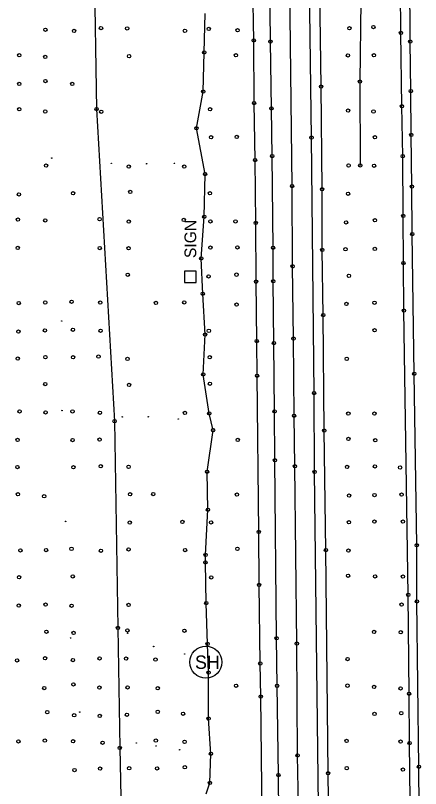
# Model space of a CAD drawing. Extents: x 20503438 to 20508873, y 7964251 to 7984667.
# Drawn here: x 20505218.6 to 20505461, y 7982806.9 to 7983269.7 of the extents above; entities that cross this region are included whole.
import ezdxf

# ---------------------------------------------------------------- set-up
doc = ezdxf.new("R2010")
doc.units = 0
for name, color, linetype in [('SurBreakLine', 7, 'Continuous'), ('SurControl', 7, 'Continuous'), ('SurDrainageArrowDown', 7, 'Continuous'), ('SurDrainageArrowUp', 7, 'Continuous'), ('SurEdgeRoadPaved', 7, 'Continuous'), ('SurEdgeShoulderPaved', 7, 'Continuous'), ('SurFenceWire', 7, 'Continuous'), ('SurNaturalCells', 7, 'Continuous'), ('SurPointsNonDTM', 7, 'Continuous'), ('SurRoadPoints', 7, 'Continuous'), ('SurSurveyPoints', 7, 'Continuous')]:
    doc.layers.add(name, color=color, linetype=linetype)

msp = doc.modelspace()

# ---------------------------------------------------------------- linework, layer by layer
at = {"layer": 'SurBreakLine'}
msp.add_lwpolyline([(20505388.09, 7982786.72), (20505387.46, 7982826.69), (20505386.97, 7982893.61), (20505385.8, 7982999.79), (20505385.32, 7983030.07), (20505384.98, 7983076.27), (20505384.47, 7983119.49), (20505384.1, 7983167.57), (20505382.15, 7983337.32), (20505379.76, 7983573.99), (20505379.24, 7983609.63), (20505378.24, 7983709.76), (20505377.29, 7983778.59), (20505376.87, 7983823.71), (20505376.2, 7983914.92), (20505375.66, 7983955.45), (20505374.47, 7984054.03), (20505371.04, 7984409.5), (20505370.34, 7984465.16)], dxfattribs=at)
at = {"layer": 'SurControl'}
for centre in [(20505240.3, 7983184.28), (20505275.98, 7983181.13), (20505297.02, 7983180.89), (20505313.71, 7983181.13), (20505246.26, 7983086.81), (20505246.45, 7983033.15), (20505282.48, 7983029.34), (20505298.08, 7983029.41), (20505315.98, 7983028.13), (20505248.53, 7982966.75), (20505285.75, 7982899.87), (20505251.54, 7982896.94), (20505301.31, 7982891.9), (20505319.88, 7982887.38), (20505257.06, 7982852.63), (20505290.94, 7982834.09), (20505302.75, 7982832.29), (20505316.82, 7982830.05)]:
    msp.add_circle(centre, 0.15, dxfattribs=at)
at = {"layer": 'SurDrainageArrowDown'}
msp.add_lwpolyline([(20505332.76, 7982803.76), (20505334.91, 7982810.26), (20505335.55, 7982827.71), (20505334.17, 7982848.71), (20505334.18, 7982876.28), (20505333.51, 7982893.44), (20505332.77, 7982917.85), (20505332.28, 7982942.23), (20505332.37, 7982946.68), (20505333.74, 7982973.81), (20505333.28, 7982996.49), (20505336.88, 7983021.4), (20505334.57, 7983031.42), (20505331, 7983054.83), (20505332.02, 7983078.67), (20505330.68, 7983103.07), (20505329.78, 7983124.21), (20505331.56, 7983149.14), (20505332.02, 7983174.71), (20505326.84, 7983202.11), (20505330.95, 7983224.07), (20505331.52, 7983247.58), (20505332.03, 7983270.82)], dxfattribs=at)
at = {"layer": 'SurDrainageArrowUp'}
msp.add_lwpolyline([(20505435.69, 7983412.57), (20505432.5, 7983412.27), (20505429.44, 7983411.43), (20505426.11, 7983408.1), (20505425.72, 7983400.28), (20505426.05, 7983374.69), (20505426.24, 7983351.03), (20505426.02, 7983326.08), (20505425.25, 7983278.5), (20505424.77, 7983230.05), (20505424.95, 7983179.92)], dxfattribs=at)
at = {"layer": 'SurEdgeRoadPaved'}
for points in [[(20505403.63, 7982474.93), (20505402.88, 7982536.9), (20505402.67, 7982576.67), (20505401.63, 7982665.51), (20505399.87, 7982796.43), (20505397.64, 7982996.42), (20505397.31, 7983043.62), (20505395.75, 7983196.59), (20505394.62, 7983287.56), (20505393.71, 7983393.22), (20505391.47, 7983583.96), (20505391.16, 7983613.2), (20505390.95, 7983649.19), (20505388.69, 7983846.62), (20505387.86, 7983937.63), (20505387.13, 7984000.04), (20505387.09, 7984002.85), (20505386.65, 7984030.88), (20505382.6, 7984465.04)], [(20505376.87, 7982720.03), (20505375.97, 7982814.93), (20505375.18, 7982868.35), (20505374.84, 7982896.8), (20505373.9, 7983003.41), (20505373.63, 7983032.61), (20505373.23, 7983073.5), (20505372.9, 7983110.52), (20505372.72, 7983130.62), (20505372.2, 7983185.46), (20505371.76, 7983214.03), (20505371.18, 7983254.01), (20505370.55, 7983308.55), (20505370.11, 7983376.99), (20505368.96, 7983469.33), (20505368.55, 7983508.46), (20505368.26, 7983546.26), (20505367.99, 7983574.82), (20505367.67, 7983598.7), (20505367.02, 7983649.08), (20505365.92, 7983751.56)], [(20505460.57, 7982745.92), (20505460.02, 7982819.87), (20505458.85, 7982918.92), (20505458.72, 7982952.55), (20505457.28, 7983055.18), (20505456.07, 7983138.84), (20505455.85, 7983167.22), (20505455.42, 7983198.13), (20505455.22, 7983224.45), (20505454.85, 7983254.02), (20505454.55, 7983292.83), (20505453.72, 7983358.98), (20505453.59, 7983387.67), (20505452.51, 7983492.09), (20505451.03, 7983612.62), (20505450.51, 7983669.13), (20505449.78, 7983725.38), (20505449.64, 7983752.99)]]:
    msp.add_lwpolyline(points, dxfattribs=at)
at = {"layer": 'SurEdgeShoulderPaved'}
for points in [[(20505406.44, 7982753), (20505405.66, 7982815.99), (20505404.36, 7982949.58), (20505403.42, 7983021.17), (20505402.75, 7983090.32), (20505402.21, 7983129.29), (20505402.08, 7983165.66), (20505401.47, 7983227.06), (20505400.04, 7983341.4), (20505399.38, 7983413.75), (20505397.66, 7983569.46), (20505397.07, 7983624.87), (20505396.26, 7983698.73), (20505395.49, 7983760.73)], [(20505366.98, 7982718.13), (20505365.41, 7982861.87), (20505365.07, 7982881.72), (20505364.41, 7982928.72), (20505364.19, 7982960.53), (20505363.22, 7983054.03), (20505362.96, 7983074.76), (20505362.61, 7983110.31), (20505362.42, 7983145.46), (20505361.97, 7983183.06), (20505361.41, 7983217.22), (20505361.15, 7983254.72), (20505360.71, 7983288.06), (20505360.6, 7983299.77), (20505360.47, 7983317.66), (20505360.11, 7983363.4), (20505359.23, 7983433.57), (20505358.71, 7983478.18), (20505357.37, 7983616.7), (20505356.33, 7983687.67), (20505355.63, 7983757.41)], [(20505454.87, 7982799.91), (20505454.43, 7982834.05), (20505454.19, 7982863.65), (20505453.63, 7982922.83), (20505451.09, 7983092.97), (20505450.78, 7983121.42), (20505450.67, 7983149.63), (20505450.35, 7983185.44), (20505449.91, 7983215.31), (20505449.29, 7983259.23), (20505449.04, 7983285.01), (20505448.83, 7983321.6), (20505448.42, 7983357.03), (20505448.19, 7983377.57), (20505447.91, 7983416.56), (20505446.96, 7983486.61), (20505445.72, 7983599.24), (20505445.42, 7983622.54), (20505445.14, 7983645.21), (20505445.01, 7983677.11), (20505444.05, 7983741.95)]]:
    msp.add_lwpolyline(points, dxfattribs=at)
at = {"layer": 'SurFenceWire'}
msp.add_lwpolyline([(20505263.07, 7983570.84), (20505264.2, 7983465.89), (20505264.6, 7983384.22), (20505265.76, 7983299.57), (20505267.13, 7983213.61), (20505277.91, 7983026.79), (20505279.9, 7982903.03), (20505280.94, 7982831.19), (20505284.45, 7982664.16), (20505302.4, 7982645.24), (20505317.11, 7982628.42), (20505340.63, 7982610.34)], dxfattribs=at)
at = {"layer": 'SurNaturalCells'}
msp.add_circle((20505332.54, 7982882.51), 9.59, dxfattribs=at)
at = {"layer": 'SurPointsNonDTM'}
for centre in [(20505267.13, 7983213.61), (20505277.91, 7983026.79), (20505279.9, 7982903.03), (20505280.94, 7982831.19)]:
    msp.add_circle(centre, 1, dxfattribs=at)
at = {"layer": 'SurRoadPoints'}
msp.add_lwpolyline([(20505326.66, 7983113.23), (20505326.66, 7983113.23), (20505326.66, 7983116.66), (20505319.8, 7983116.66), (20505319.8, 7983109.8), (20505326.66, 7983109.8), (20505326.66, 7983113.23)], dxfattribs=at)
at = {"layer": 'SurSurveyPoints'}
for centre in [(20505236.52, 7983261.11), (20505253.65, 7983260.41), (20505269.75, 7983262.13), (20505285.42, 7983261.93), (20505320.03, 7983260.48), (20505334.27, 7983261.65), (20505351.53, 7983260.86), (20505418.48, 7983261.99), (20505432.81, 7983262.76), (20505449.29, 7983259.23), (20505361.15, 7983254.72), (20505371.18, 7983254.01), (20505454.85, 7983254.02), (20505220.82, 7983245.81), (20505236.4, 7983244.85), (20505286.54, 7983245.3), (20505331.52, 7983247.58), (20505350.47, 7983245.83), (20505417.57, 7983245.74), (20505433.15, 7983245.88), (20505220.85, 7983228.72), (20505236.49, 7983230.38), (20505252.57, 7983228.7), (20505401.47, 7983227.06), (20505424.77, 7983230.05), (20505330.95, 7983224.07), (20505455.22, 7983224.45), (20505361.41, 7983217.22), (20505220.82, 7983213.48), (20505335.01, 7983213.48), (20505371.76, 7983214.03), (20505417.67, 7983212.71), (20505449.91, 7983215.31), (20505236.35, 7983212.18), (20505269.9, 7983212.06), (20505432.87, 7983212.18), (20505326.84, 7983202.11), (20505335.62, 7983196.74), (20505351.03, 7983196.97), (20505395.75, 7983196.59), (20505433.74, 7983196.73), (20505455.42, 7983198.13), (20505372.2, 7983185.46), (20505450.35, 7983185.44), (20505361.97, 7983183.06), (20505236.86, 7983179.83), (20505286.37, 7983179.18), (20505319.57, 7983179.22), (20505417.96, 7983179.86), (20505424.95, 7983179.92), (20505433.17, 7983179.7), (20505332.02, 7983174.71), (20505384.1, 7983167.57), (20505455.85, 7983167.22), (20505220.63, 7983162.55), (20505253.01, 7983163.25), (20505287.28, 7983164), (20505334.96, 7983163.28), (20505402.08, 7983165.66), (20505417.69, 7983162.95), (20505268.92, 7983147.72), (20505331.56, 7983149.14), (20505450.67, 7983149.63), (20505220.03, 7983147.45), (20505236.39, 7983146.97), (20505286.35, 7983146.28), (20505319.25, 7983147.26), (20505335.24, 7983146.36), (20505350.26, 7983146.39), (20505362.42, 7983145.46), (20505416.47, 7983145.82), (20505433.69, 7983147.03), (20505456.07, 7983138.84), (20505219.92, 7983130.55), (20505269.03, 7983130.43), (20505286.29, 7983130.28), (20505335.2, 7983130.71), (20505351.43, 7983130.78), (20505372.72, 7983130.62), (20505402.21, 7983129.29), (20505416.11, 7983129.69), (20505433.67, 7983129.95), (20505329.78, 7983124.21), (20505450.78, 7983121.42), (20505384.47, 7983119.49), (20505285.73, 7983114.46), (20505334.11, 7983113.42), (20505350.86, 7983114.5), (20505372.9, 7983110.52), (20505418.14, 7983113.8), (20505362.61, 7983110.31), (20505330.68, 7983103.07), (20505220.52, 7983097.49), (20505236.35, 7983097.83), (20505252.13, 7983098.26), (20505269.31, 7983097.81), (20505302.66, 7983097.56), (20505319.57, 7983097.9), (20505416.65, 7983097), (20505433.46, 7983097.65), (20505350.94, 7983096.55), (20505451.09, 7983092.97), (20505402.75, 7983090.32), (20505220.3, 7983080.4), (20505236.16, 7983081.09), (20505252.93, 7983081.53), (20505269.47, 7983080.89), (20505332.02, 7983078.67), (20505334.3, 7983080.88), (20505433.52, 7983081.18), (20505362.96, 7983074.76), (20505373.23, 7983073.5), (20505384.98, 7983076.27), (20505219.94, 7983064.3), (20505236.51, 7983065.11), (20505253.05, 7983065.1), (20505268.26, 7983065.45), (20505334.84, 7983065.06), (20505285.61, 7983064.08), (20505416.86, 7983064.12), (20505457.28, 7983055.18), (20505331, 7983054.83), (20505363.22, 7983054.03), (20505236.41, 7983048.97), (20505286.52, 7983048.5), (20505334.95, 7983049.16), (20505397.31, 7983043.62), (20505220.99, 7983032.63), (20505236.61, 7983032.04), (20505252.69, 7983032.67), (20505373.63, 7983032.61), (20505269.08, 7983031.82), (20505319.95, 7983031.69), (20505334.57, 7983031.42), (20505385.32, 7983030.07), (20505417.8, 7983031.3), (20505433.45, 7983031.32), (20505336.88, 7983021.4), (20505403.42, 7983021.17), (20505219.84, 7983015.6), (20505252.76, 7983015.46), (20505268.95, 7983015.8), (20505351.59, 7983015.54), (20505417.88, 7983016.17), (20505433.89, 7983015.39), (20505269.56, 7982999.79), (20505286.3, 7982999.46), (20505373.9, 7983003.41), (20505385.8, 7982999.79), (20505433.68, 7982999.68), (20505219.75, 7982999.34), (20505253.22, 7982999.23), (20505333.28, 7982996.49), (20505397.64, 7982996.42), (20505417.08, 7982999.36), (20505448.75, 7982999.06), (20505220.05, 7982983.05), (20505235.74, 7982981.81), (20505287.19, 7982983.01), (20505301.04, 7982983.17), (20505351.09, 7982982.83), (20505418.28, 7982982.25), (20505433.46, 7982982.55), (20505449.68, 7982982.83), (20505333.74, 7982973.81), (20505286.96, 7982966.04), (20505318.46, 7982966.51), (20505335.6, 7982966.2), (20505418.16, 7982966.24), (20505433.45, 7982966.64), (20505450.46, 7982966.7), (20505364.19, 7982960.53), (20505221.49, 7982949.4), (20505236.91, 7982949.64), (20505252.1, 7982950.36), (20505269.69, 7982949.26), (20505286.3, 7982949.99), (20505320.06, 7982949.65), (20505351.41, 7982950.36), (20505404.36, 7982949.58), (20505417.88, 7982949.33), (20505458.72, 7982952.55), (20505332.37, 7982946.68), (20505332.28, 7982942.23), (20505220.69, 7982933.33), (20505252.8, 7982933.88), (20505335.71, 7982933.29), (20505417.64, 7982934.29), (20505433.78, 7982933.87), (20505450.45, 7982933.72), (20505364.41, 7982928.72), (20505453.63, 7982922.83), (20505220.51, 7982916.37), (20505236.58, 7982916.96), (20505252.12, 7982916.34), (20505286.26, 7982916.82), (20505332.77, 7982917.85), (20505449.71, 7982916.98), (20505458.85, 7982918.92), (20505237.07, 7982900.76), (20505253.33, 7982900.02), (20505285.58, 7982901.53), (20505319.67, 7982901.37), (20505433.2, 7982900.61), (20505449.13, 7982900.45), (20505333.51, 7982893.44), (20505374.84, 7982896.8), (20505386.97, 7982893.61), (20505236.26, 7982884.83), (20505252.9, 7982883.74), (20505268.87, 7982884.75), (20505284.74, 7982884.7), (20505302.37, 7982884.05), (20505417.32, 7982884.41), (20505219.55, 7982883.6), (20505365.07, 7982881.72), (20505334.18, 7982876.28), (20505235.75, 7982867.02), (20505253.26, 7982869.18), (20505268.78, 7982867.34), (20505285.65, 7982867.38), (20505303.69, 7982866.88), (20505350.63, 7982868.39), (20505375.18, 7982868.35), (20505417.31, 7982868.45), (20505433.19, 7982867.67), (20505449.07, 7982866.79), (20505365.41, 7982861.87), (20505454.19, 7982863.65), (20505237.61, 7982852.58), (20505303.71, 7982852.79), (20505318.84, 7982851.68), (20505433.46, 7982851.52), (20505449.48, 7982851.99), (20505253.69, 7982850.78), (20505268.99, 7982850.38), (20505285.23, 7982851.03), (20505334.17, 7982848.71), (20505220.34, 7982835.12), (20505236.13, 7982835.57), (20505253.03, 7982835.18), (20505270.68, 7982834.25), (20505302.58, 7982835.59), (20505319.78, 7982834.82), (20505416.75, 7982835.35), (20505449.07, 7982835), (20505454.43, 7982834.05), (20505335.55, 7982827.71), (20505387.46, 7982826.69), (20505286.61, 7982819.01), (20505319.94, 7982819.57), (20505416.82, 7982819.06), (20505460.02, 7982819.87), (20505253.88, 7982817.91), (20505269.18, 7982818.82), (20505303.31, 7982818.92), (20505375.97, 7982814.93), (20505405.66, 7982815.99), (20505450.52, 7982818.18), (20505334.91, 7982810.26)]:
    msp.add_circle(centre, 1, dxfattribs=at)

# ---------------------------------------------------------------- texts
at = {"layer": 'SurNaturalCells'}
msp.add_text('SH', height=7.995, rotation=360, dxfattribs=at).set_placement((20505326.02, 7982878.51))
at = {"layer": 'SurRoadPoints'}
msp.add_text('SIGN', height=6.995, rotation=90, dxfattribs=at).set_placement((20505326.73, 7983124.44))

doc.saveas('drawing.dxf')
